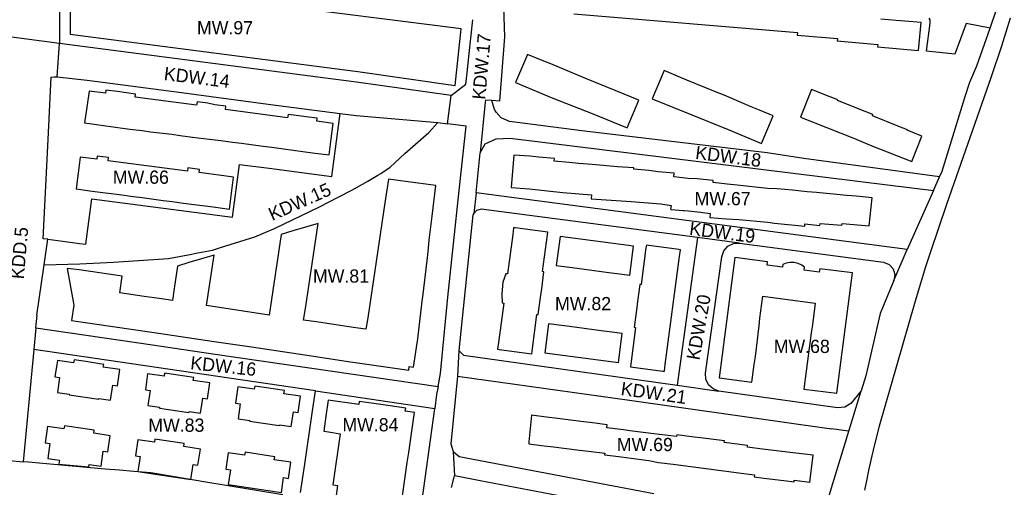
# Model space of a CAD drawing. Extents: x 7424434 to 7425898, y 5541432 to 5542659.
# Drawn here: x 7425417.1 to 7425791.2, y 5541850.5 to 5542027 of the extents above; entities that cross this region are included whole.
import ezdxf

# ---------------------------------------------------------------- set-up
doc = ezdxf.new("R2010")
doc.units = 0
for name, color, linetype in [('linie rozgraniczające', 7, 'Continuous'), ('nieprzekraczalne linie zabudowy', 7, 'Continuous'), ('obowiazujace linie zabudowy', 7, 'Continuous'), ('przeznaczenia terenów', 7, 'Continuous')]:
    doc.layers.add(name, color=color, linetype=linetype)

msp = doc.modelspace()

# ---------------------------------------------------------------- linework, layer by layer
at = {"layer": 'linie rozgraniczające'}
for p, q in [((7425432, 5542046.92), (7425432.08, 5542018.07)), ((7425599.54, 5542039.18), (7425600.19, 5542020.57)), ((7425783.55, 5542023.81), (7425786.17, 5542031.23)), ((7425586.8, 5542014.33), (7425588.17, 5542027.05)), ((7425760.89, 5542026.95), (7425760.58, 5542027.6)), ((7425760.98, 5542025.79), (7425760.89, 5542026.95)), ((7425791.17, 5542027.57), (7425787.89, 5542017.02)), ((7425759.52, 5542015.19), (7425760.98, 5542025.79)), ((7425774.58, 5542025.62), (7425770.29, 5542014.07)), ((7425783.55, 5542023.81), (7425774.58, 5542025.62)), ((7425778.55, 5542009.59), (7425783.55, 5542023.81)), ((7425432.08, 5542018.07), (7425410.14, 5542020.93)), ((7425600.19, 5542020.57), (7425598.3, 5541996.33)), ((7425431.22, 5542005.4), (7425432.08, 5542018.07)), ((7425535.48, 5542004.61), (7425432.08, 5542018.07)), ((7425787.89, 5542017.02), (7425784, 5542005.48)), ((7425586.01, 5542006.94), (7425586.8, 5542014.33)), ((7425770.29, 5542014.07), (7425759.52, 5542015.19)), ((7425775.87, 5542003.4), (7425778.55, 5542009.59)), ((7425427.79, 5541981.77), (7425428.99, 5542005.32)), ((7425428.99, 5542005.32), (7425430.06, 5542005.52)), ((7425430.06, 5542005.52), (7425431.22, 5542005.4)), ((7425431.22, 5542005.4), (7425442.51, 5542004.25)), ((7425544.23, 5542003.47), (7425535.48, 5542004.61)), ((7425585.55, 5542002.66), (7425586.01, 5542006.94)), ((7425784, 5542005.48), (7425767.09, 5541957.21)), ((7425442.51, 5542004.25), (7425476.32, 5541999.77)), ((7425580.05, 5541998.39), (7425544.23, 5542003.47)), ((7425580.05, 5541998.39), (7425585.55, 5542002.66)), ((7425774.1, 5541997.67), (7425775.87, 5542003.4)), ((7425476.32, 5541999.77), (7425510.91, 5541995.14)), ((7425578.66, 5541987.7), (7425580.05, 5541998.39)), ((7425765.49, 5541969.78), (7425774.1, 5541997.67)), ((7425510.91, 5541995.14), (7425538.05, 5541991.59)), ((7425592.88, 5541995.93), (7425590.96, 5541976.8)), ((7425592.96, 5541996.7), (7425592.88, 5541995.93)), ((7425595.44, 5541996.53), (7425592.96, 5541996.7)), ((7425596.42, 5541993.12), (7425595.44, 5541996.53)), ((7425598.3, 5541996.33), (7425595.44, 5541996.53)), ((7425597.03, 5541992.12), (7425596.42, 5541993.12)), ((7425534.97, 5541967.82), (7425538.05, 5541991.59)), ((7425538.05, 5541991.59), (7425544.14, 5541990.8)), ((7425544.14, 5541990.8), (7425574.96, 5541988.16)), ((7425598.96, 5541990.02), (7425597.03, 5541992.12)), ((7425602.12, 5541988.53), (7425598.96, 5541990.02)), ((7425571.53, 5541984.43), (7425574.96, 5541988.16)), ((7425574.96, 5541988.16), (7425578.66, 5541987.7)), ((7425585.64, 5541986.79), (7425578.66, 5541987.7)), ((7425583.07, 5541962.54), (7425585.64, 5541986.79)), ((7425630.36, 5541984.9), (7425602.12, 5541988.53)), ((7425562.54, 5541976.53), (7425571.53, 5541984.43)), ((7425592.92, 5541980.12), (7425597.04, 5541982.02)), ((7425597.04, 5541982.02), (7425602.36, 5541982.24)), ((7425602.36, 5541982.24), (7425744.89, 5541964.63)), ((7425699.43, 5541976.72), (7425630.36, 5541984.9)), ((7425425.96, 5541944.33), (7425427.79, 5541981.77)), ((7425590.96, 5541976.8), (7425592.92, 5541980.12)), ((7425556.98, 5541971.29), (7425562.54, 5541976.53)), ((7425589.44, 5541961.7), (7425590.96, 5541976.8)), ((7425713.18, 5541974.57), (7425699.43, 5541976.72)), ((7425764.53, 5541967.64), (7425713.18, 5541974.57)), ((7425497.43, 5541952.48), (7425500.02, 5541972.36)), ((7425500.02, 5541972.36), (7425511.3, 5541970.9)), ((7425511.3, 5541970.9), (7425534.97, 5541967.82)), ((7425553.52, 5541968.97), (7425556.98, 5541971.29)), ((7425548.51, 5541966), (7425552.38, 5541968.29)), ((7425552.38, 5541968.29), (7425553.52, 5541968.97)), ((7425762.22, 5541962.49), (7425764.53, 5541967.64)), ((7425764.53, 5541967.64), (7425765.49, 5541969.78)), ((7425542.5, 5541962.69), (7425548.51, 5541966)), ((7425744.89, 5541964.63), (7425762.22, 5541962.49)), ((7425530.27, 5541956.33), (7425537.4, 5541959.96)), ((7425537.4, 5541959.96), (7425542.5, 5541962.69)), ((7425578.82, 5541922.18), (7425583.07, 5541962.54)), ((7425589.44, 5541961.7), (7425588.58, 5541953.78)), ((7425752.23, 5541940.28), (7425589.44, 5541961.7)), ((7425762.22, 5541962.49), (7425752.23, 5541940.28)), ((7425442.1, 5541942.23), (7425444.34, 5541959.4)), ((7425444.34, 5541959.4), (7425497.43, 5541952.48)), ((7425513.35, 5541948.23), (7425530.27, 5541956.33)), ((7425767.09, 5541957.21), (7425761.02, 5541939.39)), ((7425588.16, 5541953.33), (7425582.88, 5541902.08)), ((7425588.58, 5541953.78), (7425588.16, 5541953.33)), ((7425589.65, 5541954.94), (7425588.58, 5541953.78)), ((7425590.07, 5541955.08), (7425589.65, 5541954.94)), ((7425591.33, 5541955.5), (7425590.07, 5541955.08)), ((7425673.12, 5541944.74), (7425591.33, 5541955.5)), ((7425505.85, 5541945.05), (7425513.35, 5541948.23)), ((7425492.86, 5541941.01), (7425505.85, 5541945.05)), ((7425673.12, 5541944.74), (7425665.35, 5541889)), ((7425688.98, 5541942.66), (7425673.12, 5541944.74)), ((7425427.69, 5541944.1), (7425425.96, 5541944.33)), ((7425426.3, 5541934.49), (7425427.69, 5541944.1)), ((7425427.69, 5541944.1), (7425433.39, 5541943.36)), ((7425433.39, 5541943.36), (7425439.59, 5541942.55)), ((7425439.59, 5541942.55), (7425442.1, 5541942.23)), ((7425489.92, 5541940), (7425492.86, 5541941.01)), ((7425683, 5541939.7), (7425684.54, 5541941.46)), ((7425684.54, 5541941.46), (7425686.64, 5541942.5)), ((7425686.64, 5541942.5), (7425688.98, 5541942.66)), ((7425688.98, 5541942.66), (7425743.33, 5541935.5)), ((7425473.23, 5541936.83), (7425477.24, 5541937.58)), ((7425477.24, 5541937.58), (7425480.65, 5541938.27)), ((7425480.65, 5541938.27), (7425484.32, 5541938.96)), ((7425484.32, 5541938.96), (7425489.92, 5541940)), ((7425676.05, 5541893.55), (7425682.24, 5541937.49)), ((7425682.24, 5541937.49), (7425683, 5541939.7)), ((7425747.26, 5541928.5), (7425752.23, 5541940.28)), ((7425761.02, 5541939.39), (7425759.08, 5541933.29)), ((7425423.55, 5541915.42), (7425426.3, 5541934.49)), ((7425426.3, 5541934.49), (7425439.77, 5541934.86)), ((7425439.77, 5541934.86), (7425452.51, 5541935.44)), ((7425452.51, 5541935.44), (7425473.23, 5541936.83)), ((7425743.33, 5541935.5), (7425745.45, 5541934.6)), ((7425745.45, 5541934.6), (7425746.99, 5541932.93)), ((7425759.08, 5541933.29), (7425755.06, 5541919.89)), ((7425746.99, 5541932.93), (7425747.65, 5541930.75)), ((7425747.65, 5541930.75), (7425747.26, 5541928.5)), ((7425747.26, 5541928.5), (7425742.02, 5541916.04)), ((7425575.94, 5541893.34), (7425578.82, 5541922.18)), ((7425755.06, 5541919.89), (7425741.74, 5541873.49)), ((7425423.14, 5541910.66), (7425423.61, 5541915.41)), ((7425423.61, 5541915.41), (7425423.55, 5541915.42)), ((7425742.02, 5541916.04), (7425736.65, 5541892.48)), ((7425423.14, 5541910.66), (7425422.36, 5541902.41)), ((7425423.14, 5541910.66), (7425467.21, 5541904.19)), ((7425467.21, 5541904.19), (7425489.95, 5541900.83)), ((7425422.36, 5541902.41), (7425418.37, 5541860.04)), ((7425528.74, 5541886.85), (7425422.36, 5541902.41)), ((7425489.95, 5541900.83), (7425526.54, 5541895.52)), ((7425582.88, 5541902.08), (7425582.46, 5541892.43)), ((7425582.88, 5541902.08), (7425584.7, 5541900.38)), ((7425584.7, 5541900.38), (7425665.35, 5541889)), ((7425526.54, 5541895.52), (7425575.06, 5541888.48)), ((7425575.06, 5541888.48), (7425575.94, 5541893.34)), ((7425582.46, 5541892.43), (7425579.88, 5541866.81)), ((7425582.46, 5541892.43), (7425647.34, 5541883.27)), ((7425676.18, 5541891.21), (7425676.05, 5541893.55)), ((7425736.65, 5541892.48), (7425734.91, 5541886.8)), ((7425575.06, 5541888.48), (7425574.53, 5541885.52)), ((7425665.35, 5541889), (7425681.15, 5541886.77)), ((7425677.2, 5541889.11), (7425676.18, 5541891.21)), ((7425678.94, 5541887.55), (7425677.2, 5541889.11)), ((7425527.53, 5541878.45), (7425528.74, 5541886.85)), ((7425528.74, 5541886.85), (7425573.8, 5541880.23)), ((7425574.53, 5541885.52), (7425573.8, 5541880.23)), ((7425681.15, 5541886.77), (7425678.94, 5541887.55)), ((7425725.95, 5541880.46), (7425681.15, 5541886.77)), ((7425730.25, 5541871.57), (7425734.91, 5541886.8)), ((7425734.91, 5541886.8), (7425730.99, 5541882.11)), ((7425647.34, 5541883.27), (7425723.62, 5541872.51)), ((7425730.99, 5541882.11), (7425728.66, 5541880.7)), ((7425524.73, 5541859.15), (7425527.53, 5541878.45)), ((7425567.48, 5541834.53), (7425573.8, 5541880.23)), ((7425728.66, 5541880.7), (7425725.95, 5541880.46)), ((7425741.74, 5541873.49), (7425739.83, 5541866.13)), ((7425722.86, 5541847.26), (7425730.25, 5541871.57)), ((7425730.1, 5541871.59), (7425723.62, 5541872.51)), ((7425730.25, 5541871.57), (7425730.1, 5541871.59)), ((7425579.88, 5541866.81), (7425580.72, 5541863.9)), ((7425739.83, 5541866.13), (7425738.54, 5541860.72)), ((7425580.72, 5541863.9), (7425581.34, 5541854.71)), ((7425580.72, 5541863.9), (7425583.05, 5541862.1)), ((7425413.19, 5541860.48), (7425418.37, 5541860.04)), ((7425420.36, 5541859.87), (7425418.37, 5541860.04)), ((7425425.75, 5541859.38), (7425420.36, 5541859.87)), ((7425449.34, 5541857.32), (7425425.75, 5541859.38)), ((7425523.18, 5541848.5), (7425524.73, 5541859.15)), ((7425583.05, 5541862.1), (7425656.63, 5541848.13)), ((7425738.54, 5541860.72), (7425737.65, 5541856.71)), ((7425454.74, 5541856.84), (7425449.34, 5541857.32)), ((7425460.14, 5541856.38), (7425454.74, 5541856.84)), ((7425466.6, 5541855.82), (7425460.14, 5541856.38)), ((7425488.88, 5541852.12), (7425466.6, 5541855.82)), ((7425581.38, 5541854.84), (7425591.03, 5541853.01)), ((7425737.65, 5541856.71), (7425736.98, 5541853.51)), ((7425494.23, 5541851.23), (7425488.88, 5541852.12)), ((7425516.46, 5541847.52), (7425494.23, 5541851.23)), ((7425591.03, 5541853.01), (7425622.72, 5541846.9)), ((7425736.98, 5541853.51), (7425736.17, 5541849.39))]:
    msp.add_line(p, q, dxfattribs=at)
msp.add_lwpolyline([(7425580.13, 5541850.37), (7425581.34, 5541854.71), (7425581.38, 5541854.84)], dxfattribs=at)
at = {"layer": 'nieprzekraczalne linie zabudowy'}
msp.add_lwpolyline([(7425581.48, 5542002.23), (7425583.77, 5542023.58), (7425436.01, 5542042.38), (7425435.98, 5542041.67), (7425436.07, 5542021.58), (7425536, 5542008.58), (7425544.77, 5542007.43)], close=True, dxfattribs=at)
at = {"layer": 'obowiazujace linie zabudowy'}
msp.add_lwpolyline([(7425626.34, 5542029.32), (7425710.79, 5542022.16), (7425710.71, 5542021.25), (7425725.94, 5542019.91), (7425725.86, 5542019), (7425741.13, 5542017.66), (7425741.06, 5542016.8), (7425756.59, 5542015.44), (7425757.54, 5542026), (7425751.44, 5542026.52), (7425748.14, 5542026.8), (7425742.29, 5542027.3)], dxfattribs=at)
for points in [[(7425608.92, 5542013.88), (7425604.37, 5542003.26), (7425618.41, 5541997.39), (7425633.32, 5541991.56), (7425646.56, 5541986.22), (7425650.87, 5541996.69), (7425645.32, 5541998.92), (7425641.91, 5542000.28), (7425631.13, 5542004.69), (7425628.09, 5542005.93), (7425617.61, 5542010.33), (7425614.37, 5542011.58)], [(7425701.67, 5541990.67), (7425696.53, 5541992.83), (7425693.33, 5541994.18), (7425683.15, 5541998.58), (7425679.92, 5541999.85), (7425669.02, 5542004.25), (7425665.81, 5542005.6), (7425660.42, 5542007.85), (7425655.93, 5541997.15), (7425670.97, 5541991.07), (7425684.62, 5541985.56), (7425697.28, 5541980.33)], [(7425732.34, 5541982.14), (7425738.9, 5541979.45), (7425754.03, 5541973.44), (7425757.86, 5541983.08), (7425752.3, 5541985.29), (7425752.37, 5541985.47), (7425749.16, 5541986.75), (7425739.14, 5541990.74), (7425739.31, 5541991.17), (7425736.45, 5541992.31), (7425725.89, 5541996.5), (7425726.01, 5541996.79), (7425722.75, 5541998.08), (7425716.16, 5542000.69), (7425712, 5541990.23)], [(7425493.09, 5541981.41), (7425497.43, 5541980.83), (7425500.83, 5541980.4), (7425509.03, 5541979.27), (7425512.28, 5541978.88), (7425516.72, 5541978.21), (7425527.6, 5541976.81), (7425533.97, 5541975.99), (7425534.72, 5541982.02), (7425535.45, 5541987.89), (7425529.25, 5541988.67), (7425529.4, 5541989.88), (7425525.3, 5541990.39), (7425522.49, 5541990.71), (7425518.42, 5541991.22), (7425518.26, 5541990.02), (7425494.73, 5541993.11), (7425494.9, 5541994.37), (7425490.72, 5541994.89), (7425488.12, 5541995.46), (7425484.05, 5541995.99), (7425483.87, 5541994.82), (7425460.63, 5541997.84), (7425460.77, 5541998.97), (7425453.95, 5541999.88), (7425449.59, 5542000.46), (7425449.43, 5541999.28), (7425443.25, 5542000.07), (7425442.39, 5541993.95), (7425441.56, 5541988.05), (7425443.39, 5541987.8), (7425447.87, 5541987.2), (7425458.7, 5541985.74), (7425463.28, 5541985.2), (7425466.51, 5541984.69), (7425474.51, 5541983.75), (7425477.68, 5541983.3), (7425482.29, 5541982.71), (7425493.09, 5541981.41)], [(7425497.85, 5541967.62), (7425484.81, 5541969.3), (7425484.98, 5541970.48), (7425480.61, 5541971.04), (7425480.47, 5541969.86), (7425450.47, 5541973.73), (7425450.59, 5541974.97), (7425446.34, 5541975.53), (7425446.17, 5541974.34), (7425439.93, 5541975.15), (7425439.16, 5541969.02), (7425438.42, 5541963.11), (7425444.46, 5541962.33), (7425455.65, 5541960.88), (7425459.92, 5541960.29), (7425463.3, 5541959.84), (7425471.28, 5541958.78), (7425474.69, 5541958.33), (7425478.96, 5541957.78), (7425490.12, 5541956.31), (7425496.27, 5541955.5), (7425497.05, 5541961.47)], [(7425609.68, 5541975.49), (7425603.67, 5541975.91), (7425602.7, 5541963.67), (7425609.44, 5541963.2), (7425622.2, 5541961.79), (7425633, 5541960.95), (7425632.88, 5541959.32), (7425647.98, 5541958.31), (7425659.26, 5541957.51), (7425663.06, 5541956.91), (7425662.87, 5541955.45), (7425663.18, 5541955.4), (7425667.61, 5541955.02), (7425668.01, 5541954.95), (7425669.67, 5541954.81), (7425674.15, 5541954.28), (7425677.9, 5541953.88), (7425677.73, 5541952.35), (7425683.99, 5541951.81), (7425688.73, 5541951.54), (7425699.59, 5541950.56), (7425702.11, 5541950.19), (7425713.6, 5541949.06), (7425713.64, 5541949.88), (7425719.26, 5541949.35), (7425719.35, 5541950.11), (7425727.61, 5541949.43), (7425727.66, 5541950.12), (7425737.94, 5541949.2), (7425738.98, 5541959.73), (7425732.96, 5541960.34), (7425729.43, 5541960.69), (7425717.97, 5541961.73), (7425714.43, 5541962.07), (7425708.92, 5541962.6), (7425703.2, 5541963.17), (7425699.51, 5541963.32), (7425688.04, 5541964.55), (7425684.3, 5541964.89), (7425678.97, 5541965.5), (7425679.04, 5541966.34), (7425672.98, 5541966.87), (7425669.51, 5541967.1), (7425664.16, 5541967.69), (7425664.25, 5541969.04), (7425658.23, 5541969.58), (7425654.7, 5541970.13), (7425649.02, 5541970.59), (7425649.07, 5541971.1), (7425642.9, 5541971.47), (7425633.31, 5541972.35), (7425628.1, 5541972.77), (7425624.58, 5541973.12), (7425618.94, 5541973.56), (7425619.01, 5541974.64), (7425613.17, 5541975.11)], [(7425529.8, 5541950.12), (7425520.18, 5541947.32), (7425515.79, 5541945.88), (7425511.27, 5541915.49), (7425487.64, 5541919.06), (7425490.54, 5541938.16), (7425480.95, 5541935.27), (7425476.64, 5541933.99), (7425475.38, 5541925.45), (7425474.72, 5541920.95), (7425469.79, 5541921.68), (7425464.1, 5541922.51), (7425454.88, 5541923.85), (7425455.79, 5541930.17), (7425439.46, 5541932.53), (7425434.95, 5541933.07), (7425437.5, 5541919.27), (7425436.64, 5541913.48), (7425467.86, 5541908.87), (7425490.54, 5541905.49), (7425490.55, 5541905.53), (7425504.55, 5541903.43), (7425527.24, 5541900.08), (7425541.12, 5541897.99), (7425563.98, 5541894.61), (7425564.22, 5541896.07), (7425565.79, 5541895.84), (7425567.38, 5541906.54), (7425569.09, 5541920.73), (7425569.44, 5541923.37), (7425571.22, 5541938.22), (7425571.52, 5541940.86), (7425571.77, 5541943.75), (7425572.86, 5541952.81), (7425574.25, 5541964.4), (7425562.83, 5541965.95), (7425556.34, 5541966.83), (7425555.01, 5541957.88), (7425548.51, 5541914.49), (7425547.85, 5541910.1), (7425543.03, 5541910.81), (7425529.19, 5541912.89), (7425524.3, 5541913.59), (7425524.96, 5541917.98)], [(7425604.21, 5541948.39), (7425603.61, 5541948.47), (7425603.27, 5541945.89), (7425601.32, 5541931.02), (7425600.72, 5541931.1), (7425599.56, 5541927.91), (7425599.11, 5541923.44), (7425599.26, 5541920.08), (7425599.86, 5541920), (7425597.9, 5541905.13), (7425597.56, 5541902.55), (7425598.16, 5541902.47), (7425610.47, 5541900.85), (7425610.61, 5541901.89), (7425612.43, 5541915.72), (7425612.93, 5541915.65), (7425613.77, 5541922.1), (7425614.21, 5541925.39), (7425615.06, 5541931.83), (7425614.57, 5541931.9), (7425616.39, 5541945.73), (7425616.52, 5541946.77)], [(7425621.14, 5541945.11), (7425619.71, 5541934.18), (7425624.66, 5541933.53), (7425627.64, 5541933.13), (7425639.59, 5541931.56), (7425642.56, 5541931.17), (7425647.52, 5541930.51), (7425648.95, 5541941.44)], [(7425666.27, 5541937.59), (7425666.61, 5541940.17), (7425666.02, 5541940.25), (7425653.75, 5541941.87), (7425653.61, 5541940.83), (7425651.79, 5541926.99), (7425651.3, 5541927.06), (7425650.45, 5541920.62), (7425650.02, 5541917.33), (7425649.17, 5541910.88), (7425649.67, 5541910.82), (7425647.85, 5541896.98), (7425647.71, 5541895.95), (7425659.96, 5541894.33), (7425660.56, 5541894.25), (7425660.9, 5541896.83)], [(7425717.54, 5541919.97), (7425717.54, 5541919.97), (7425716.46, 5541911.73), (7425716.05, 5541908.79), (7425714.49, 5541897.19), (7425714.12, 5541894.27), (7425713.26, 5541887.53), (7425725.65, 5541885.94), (7425731.64, 5541931.4), (7425719.22, 5541932.95), (7425719.06, 5541931.7), (7425713.32, 5541932.45), (7425713.46, 5541933.52), (7425712.44, 5541934.3), (7425711.14, 5541934.96), (7425709.56, 5541935.35), (7425708.09, 5541935.39), (7425706.55, 5541935.1), (7425705.29, 5541934.57), (7425705.15, 5541933.54), (7425699.37, 5541934.32), (7425699.54, 5541935.55), (7425687.23, 5541937.22), (7425681.22, 5541891.78), (7425693.62, 5541890.12), (7425694.5, 5541896.79), (7425694.96, 5541899.78), (7425696.4, 5541911.39), (7425696.66, 5541914.34), (7425697.78, 5541922.61)], [(7425643.18, 5541897.59), (7425644.63, 5541908.52), (7425639.67, 5541909.18), (7425636.7, 5541909.57), (7425624.74, 5541911.14), (7425621.76, 5541911.53), (7425616.81, 5541912.18), (7425615.37, 5541901.27)], [(7425431.31, 5541898.27), (7425430.36, 5541892.15), (7425432.1, 5541891.86), (7425431.31, 5541886.25), (7425435.74, 5541885.61), (7425435.7, 5541885.31), (7425446.9, 5541883.7), (7425446.94, 5541883.97), (7425451.35, 5541883.33), (7425452.22, 5541888.98), (7425453.99, 5541888.72), (7425454.91, 5541894.85), (7425448.62, 5541895.77), (7425448.85, 5541896.85), (7425442, 5541897.93), (7425437.63, 5541898.57), (7425437.43, 5541897.43)], [(7425465.38, 5541893.26), (7425464.57, 5541887.19), (7425466.35, 5541886.95), (7425465.51, 5541881.27), (7425469.9, 5541880.63), (7425469.87, 5541880.34), (7425480.96, 5541878.72), (7425481.01, 5541879.02), (7425485.39, 5541878.38), (7425486.26, 5541884.05), (7425488.04, 5541883.79), (7425488.92, 5541889.85), (7425482.61, 5541890.72), (7425482.78, 5541891.88), (7425476.04, 5541892.92), (7425471.79, 5541893.51), (7425471.6, 5541892.4)], [(7425499.44, 5541888.34), (7425498.6, 5541882.15), (7425500.32, 5541881.92), (7425499.52, 5541876.27), (7425503.96, 5541875.65), (7425503.91, 5541875.36), (7425515.11, 5541873.7), (7425515.13, 5541874.01), (7425519.56, 5541873.32), (7425520.42, 5541878.95), (7425522.21, 5541878.67), (7425523.12, 5541884.84), (7425516.87, 5541885.76), (7425517.06, 5541886.95), (7425512.74, 5541887.57), (7425510.24, 5541887.97), (7425505.84, 5541888.62), (7425505.68, 5541887.42)], [(7425563.98, 5541863.55), (7425565.29, 5541872.52), (7425566.18, 5541878.66), (7425562.64, 5541879.17), (7425562.85, 5541880.33), (7425556.98, 5541881.21), (7425550.77, 5541882.1), (7425545.32, 5541882.88), (7425545.16, 5541881.69), (7425533.58, 5541883.37), (7425532.7, 5541877.25), (7425531.89, 5541871.64), (7425533.67, 5541871.36), (7425538.1, 5541870.67), (7425535.31, 5541851.35), (7425537.08, 5541851.11), (7425536.29, 5541845.44), (7425545.21, 5541844.25), (7425544.78, 5541841.28), (7425560.4, 5541839.01), (7425561.72, 5541848.09), (7425563.43, 5541859.79), (7425563.98, 5541863.55)], [(7425609.41, 5541867.58), (7425609.32, 5541866.85), (7425615.2, 5541866.11), (7425618.63, 5541865.68), (7425628.53, 5541864.44), (7425631.85, 5541864.02), (7425631.85, 5541864.02), (7425638.02, 5541863.25), (7425637.95, 5541862.71), (7425643.39, 5541862.02), (7425646.98, 5541861.5), (7425654.69, 5541860.53), (7425658.29, 5541859.83), (7425663.92, 5541859.13), (7425690.6, 5541855.6), (7425694.6, 5541855.09), (7425694.51, 5541854.38), (7425698.18, 5541853.92), (7425705.65, 5541852.99), (7425709.52, 5541852.51), (7425709.6, 5541853.1), (7425715.53, 5541852.35), (7425716.81, 5541862.54), (7425710.26, 5541863.36), (7425696.57, 5541864.97), (7425691.91, 5541865.55), (7425691.99, 5541866.19), (7425683.14, 5541867.29), (7425683.22, 5541867.91), (7425674.14, 5541869.05), (7425671.8, 5541869.36), (7425665.23, 5541870.18), (7425665.16, 5541869.6), (7425656.55, 5541870.67), (7425647.5, 5541871.8), (7425645.16, 5541872.09), (7425638.81, 5541872.89), (7425638.96, 5541874.03), (7425632.55, 5541874.83), (7425630.05, 5541875.14), (7425619.33, 5541876.49), (7425616.91, 5541876.79), (7425610.41, 5541877.6)], [(7425451.25, 5541869.91), (7425445.02, 5541870.84), (7425445.18, 5541871.94), (7425434, 5541873.63), (7425433.79, 5541872.45), (7425427.58, 5541873.34), (7425426.71, 5541867.17), (7425428.47, 5541866.94), (7425427.68, 5541861.3), (7425432.11, 5541860.61), (7425431.9, 5541859.19), (7425443.18, 5541858.17), (7425443.36, 5541859.04), (7425447.77, 5541858.41), (7425448.6, 5541864.03), (7425450.38, 5541863.78)], [(7425461.71, 5541868.4), (7425460.81, 5541862.34), (7425462.59, 5541862.07), (7425461.74, 5541856.39), (7425481.76, 5541853.41), (7425482.6, 5541859.09), (7425484.38, 5541858.82), (7425485.4, 5541864.86), (7425479.1, 5541865.8), (7425479.22, 5541866.95), (7425468.14, 5541868.62), (7425467.97, 5541867.46)], [(7425495.79, 5541863.41), (7425494.92, 5541857.32), (7425496.68, 5541857.06), (7425495.85, 5541851.41), (7425515.92, 5541848.41), (7425516.76, 5541854.06), (7425518.54, 5541853.79), (7425519.44, 5541859.88), (7425513.21, 5541860.83), (7425513.37, 5541861.98), (7425502.2, 5541863.69), (7425502.02, 5541862.51)]]:
    msp.add_lwpolyline(points, close=True, dxfattribs=at)

# ---------------------------------------------------------------- texts
at = {"layer": 'przeznaczenia terenów'}
for s, p in [('MW.97', (7425484.02, 5542021.52)), ('MW.66', (7425452.25, 5541965.06)), ('MW.67', (7425671.96, 5541956.95)), ('MW.81', (7425527.83, 5541927.72)), ('MW.82', (7425619.26, 5541917.3)), ('MW.68', (7425701.86, 5541901.15)), ('MW.83', (7425465.64, 5541871.38)), ('MW.84', (7425538.94, 5541871.55)), ('MW.69', (7425642.59, 5541864.07))]:
    msp.add_text(s, height=5, dxfattribs=at).set_placement(p)
for s, rotation, p in [('KDW.17', 85, (7425592.9, 5541996.71)), ('KDW.14', 352.9677, (7425471.33, 5542004.27)), ('KDW.18', 352.757, (7425672.06, 5541974.49)), ('KDW.15', 23.9677, (7425512.44, 5541950.94)), ('KDD.5', 85, (7425418.59, 5541928.89)), ('KDW.19', 352.757, (7425669.79, 5541945.78)), ('KDW.20', 80, (7425673.79, 5541898.2)), ('KDW.16', 353.9553, (7425481.35, 5541895.03)), ('KDW.21', 352, (7425643.89, 5541885.31))]:
    msp.add_text(s, height=5, rotation=rotation, dxfattribs=at).set_placement(p)

doc.saveas('drawing.dxf')
